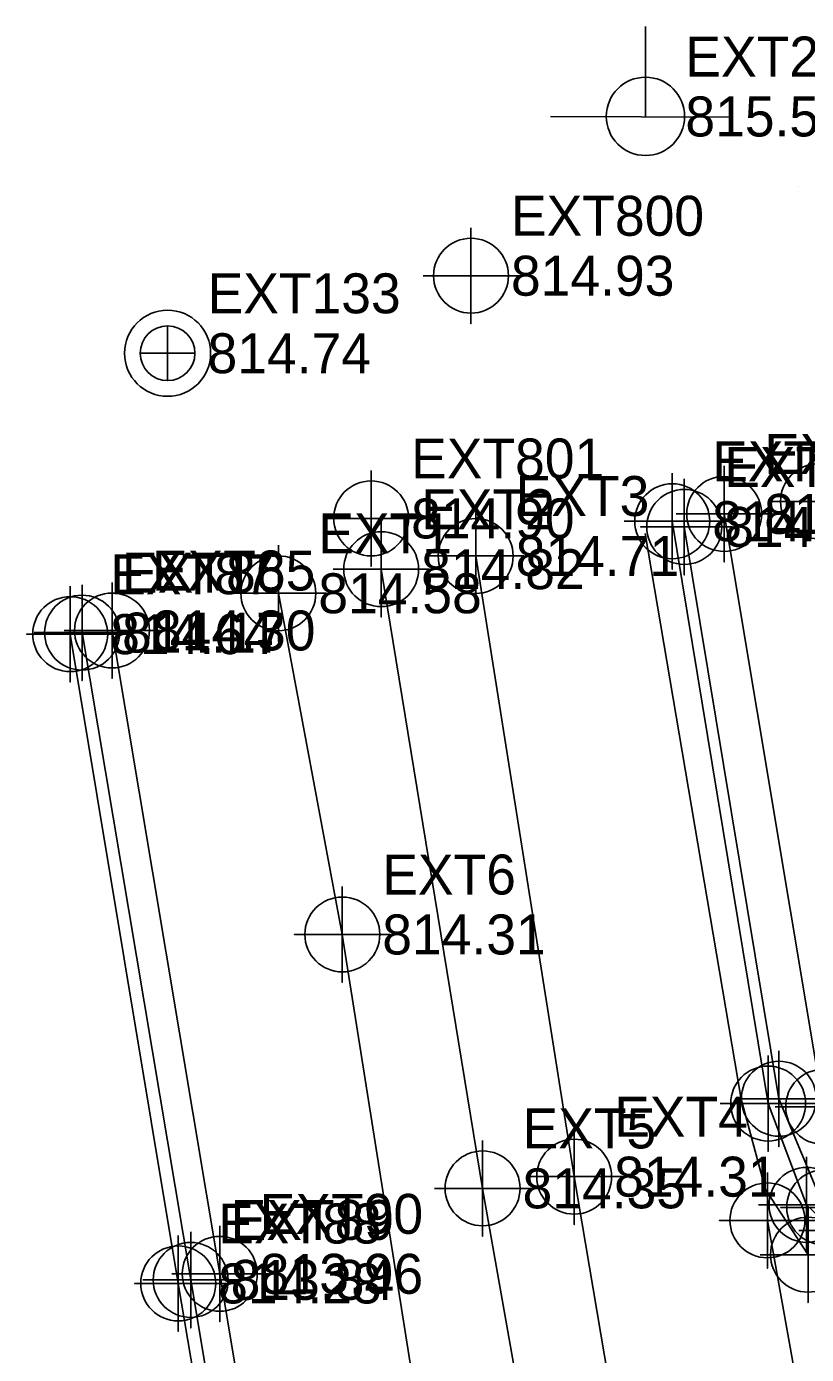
# Model space of a CAD drawing. Extents: x 1762120 to 1766775, y 709485 to 712965.
# Drawn here: x 1763761.7 to 1763810.5, y 712876.9 to 712960 of the extents above; entities that cross this region are included whole.
import ezdxf

# ---------------------------------------------------------------- set-up
doc = ezdxf.new("R2010")
doc.units = 0
for name, color, linetype in [('Exist DTM Crownline', 7, 'Continuous'), ('Exist DTM Crownline Cogo Elevation', 7, 'Continuous'), ('Exist DTM Crownline Cogo Number', 7, 'Continuous'), ('Exist DTM Crownline Cogo Point CELL', 7, 'Continuous'), ('Exist DTM Drainline', 7, 'Continuous'), ('Exist DTM Drainline Cogo Elevation', 7, 'Continuous'), ('Exist DTM Drainline Cogo Number', 7, 'Continuous'), ('Exist DTM Drainline Cogo Point CELL', 7, 'Continuous'), ('Exist DTM QL2 LIDAR Elevation Point', 7, 'Continuous'), ('Exist Roads Curbs', 7, 'Continuous'), ('Exist Roads Curbs Cogo Elevation', 7, 'Continuous'), ('Exist Roads Curbs Cogo Number', 7, 'Continuous'), ('Exist Roads Curbs Cogo Point CELL', 7, 'Continuous'), ('Exist Roads EOP', 7, 'Continuous'), ('Exist Roads EOP Cogo Elevation', 7, 'Continuous'), ('Exist Roads EOP Cogo Number', 7, 'Continuous'), ('Exist Roads EOP Cogo Point CELL', 7, 'Continuous'), ('Exist Roads EOP Other', 7, 'Continuous'), ('Exist Roads EOP Other Cogo Elevation', 7, 'Continuous'), ('Exist Roads EOP Other Cogo Number', 7, 'Continuous'), ('Exist Roads EOP Other Cogo Point CELL', 7, 'Continuous'), ('Exist Roads EOT', 7, 'Continuous'), ('Exist Roads EOT Cogo Elevation', 7, 'Continuous'), ('Exist Roads EOT Cogo Number', 7, 'Continuous'), ('Exist Roads EOT Cogo Point CELL', 7, 'Continuous'), ('Exist Utilities Power Joint Use Telephone CELL', 7, 'Continuous'), ('Exist Utilities Power Joint Use Telephone Cogo Elevation', 7, 'Continuous'), ('Exist Utilities Power Joint Use Telephone Cogo Number', 7, 'Continuous'), ('Exist Utilities Sanitary Sewer Manhole CELL', 7, 'Continuous'), ('Exist Utilities Sanitary Sewer Manhole Cogo Elevation', 7, 'Continuous'), ('Exist Utilities Sanitary Sewer Manhole Cogo Number', 7, 'Continuous'), ('Exist Utilities Sanitary Sewer UG Line Cogo Elevation', 7, 'Continuous'), ('Exist Utilities Sanitary Sewer UG Line Cogo Number', 7, 'Continuous'), ('Exist Utilities Sanitary Sewer UG Line Cogo Point CELL', 7, 'Continuous'), ('Exist Utilities Water UG Line SUE LOS C Cogo Elevation', 7, 'Continuous'), ('Exist Utilities Water UG Line SUE LOS C Cogo Number', 7, 'Continuous'), ('Exist Utilities Water UG Line SUE LOS C Cogo Point CELL', 7, 'Continuous')]:
    doc.layers.add(name, color=color, linetype=linetype)

msp = doc.modelspace()

# ---------------------------------------------------------------- linework, layer by layer
at = {"layer": 'Exist DTM Crownline'}
msp.add_lwpolyline([(1763783.92, 712926.058), (1763790.262, 712887.319), (1763795.183, 712859.532), (1763803.032, 712808.629), (1763808.926, 712776.275), (1763814.523, 712743.371), (1763820.27, 712708.85), (1763825.749, 712675.916), (1763832.222, 712637.522), (1763836.733, 712610.54), (1763843.626, 712568.925)], dxfattribs=at)
at = {"layer": 'Exist DTM Crownline Cogo Point CELL'}
for points in [[(1763783.92, 712929.058), (1763783.92, 712923.058), (1763783.92, 712926.058), (1763786.92, 712926.058), (1763780.92, 712926.058)], [(1763790.262, 712890.319), (1763790.262, 712884.319), (1763790.262, 712887.319), (1763793.262, 712887.319), (1763787.262, 712887.319)]]:
    msp.add_lwpolyline(points, dxfattribs=at)
for centre in [(1763783.92, 712926.058), (1763790.262, 712887.319)]:
    msp.add_circle(centre, 2.344, dxfattribs=at)
at = {"layer": 'Exist DTM Drainline'}
for points in [[(1763825.876, 712879.289), (1763821.264, 712879.254), (1763815.856, 712881.247), (1763810.53, 712886.287), (1763808.124, 712892.627), (1763802.125, 712929.057)], [(1763765.212, 712922.089), (1763772.003, 712881.594), (1763778.522, 712842.61), (1763780.745, 712828.822)]]:
    msp.add_lwpolyline(points, dxfattribs=at)
at = {"layer": 'Exist DTM Drainline Cogo Point CELL'}
for points in [[(1763802.125, 712932.057), (1763802.125, 712926.057), (1763802.125, 712929.057), (1763805.125, 712929.057), (1763799.125, 712929.057)], [(1763765.212, 712925.089), (1763765.212, 712919.089), (1763765.212, 712922.089), (1763768.212, 712922.089), (1763762.212, 712922.089)], [(1763808.124, 712895.627), (1763808.124, 712889.627), (1763808.124, 712892.627), (1763811.124, 712892.627), (1763805.124, 712892.627)], [(1763810.53, 712889.287), (1763810.53, 712883.287), (1763810.53, 712886.287), (1763813.53, 712886.287), (1763807.53, 712886.287)], [(1763772.003, 712884.594), (1763772.003, 712878.594), (1763772.003, 712881.594), (1763775.003, 712881.594), (1763769.003, 712881.594)]]:
    msp.add_lwpolyline(points, dxfattribs=at)
for centre in [(1763802.125, 712929.057), (1763765.212, 712922.089), (1763808.124, 712892.627), (1763810.53, 712886.287), (1763772.003, 712881.594)]:
    msp.add_circle(centre, 2.344, dxfattribs=at)
at = {"layer": 'Exist DTM QL2 LIDAR Elevation Point'}
msp.add_line((1763810, 712950), (1763810, 712950), dxfattribs=at)
at = {"layer": 'Exist Roads Curbs'}
for points in [[(1763844.782, 712885.226), (1763839.757, 712882.468), (1763825.898, 712880.05), (1763820.844, 712880.062), (1763816.547, 712881.733), (1763811.628, 712886.133), (1763808.794, 712892.927), (1763802.875, 712928.703)], [(1763764.468, 712921.993), (1763771.224, 712881.371), (1763777.799, 712842.52), (1763785.017, 712799.156), (1763793.002, 712751.297), (1763798.517, 712717.85), (1763798.751, 712716.41), (1763801.856, 712697.916), (1763802.154, 712696.936), (1763804.688, 712681.498), (1763811.149, 712642.967), (1763816.501, 712611.824), (1763823.372, 712570.121)]]:
    msp.add_lwpolyline(points, dxfattribs=at)
at = {"layer": 'Exist Roads Curbs Cogo Point CELL'}
for points in [[(1763802.875, 712931.703), (1763802.875, 712925.703), (1763802.875, 712928.703), (1763800.145, 712928.703), (1763805.875, 712928.703)], [(1763764.468, 712924.993), (1763764.468, 712918.993), (1763764.468, 712921.993), (1763761.738, 712921.993), (1763767.468, 712921.993)], [(1763808.794, 712895.927), (1763808.794, 712889.927), (1763808.794, 712892.927), (1763806.064, 712892.927), (1763811.794, 712892.927)], [(1763811.628, 712889.133), (1763811.628, 712883.133), (1763811.628, 712886.133), (1763808.898, 712886.133), (1763814.628, 712886.133)], [(1763771.224, 712884.371), (1763771.224, 712878.371), (1763771.224, 712881.371), (1763768.494, 712881.371), (1763774.224, 712881.371)]]:
    msp.add_lwpolyline(points, dxfattribs=at)
for centre in [(1763802.875, 712928.703), (1763764.468, 712921.993), (1763808.794, 712892.927), (1763811.628, 712886.133), (1763771.224, 712881.371)]:
    msp.add_circle(centre, 2.344, dxfattribs=at)
at = {"layer": 'Exist Roads EOP'}
for points in [[(1763810.619, 712883.17), (1763807.953, 712887.241), (1763806.443, 712892.894), (1763800.436, 712928.3)], [(1763767.083, 712922.223), (1763773.823, 712881.974), (1763780.335, 712842.895), (1763788.848, 712791.154), (1763795.539, 712751.806), (1763801.2, 712718.139), (1763807.385, 712682.013), (1763813.812, 712643.387), (1763818.936, 712612.35), (1763825.965, 712570.729)]]:
    msp.add_lwpolyline(points, dxfattribs=at)
at = {"layer": 'Exist Roads EOP Cogo Point CELL'}
for points in [[(1763767.083, 712925.223), (1763767.083, 712919.223), (1763767.083, 712922.223), (1763770.083, 712922.223), (1763764.083, 712922.223)], [(1763810.619, 712886.17), (1763810.619, 712880.17), (1763810.619, 712883.17), (1763813.619, 712883.17), (1763807.619, 712883.17)], [(1763773.823, 712884.974), (1763773.823, 712878.974), (1763773.823, 712881.974), (1763776.823, 712881.974), (1763770.823, 712881.974)]]:
    msp.add_lwpolyline(points, dxfattribs=at)
for centre in [(1763767.083, 712922.223), (1763810.619, 712883.17), (1763773.823, 712881.974)]:
    msp.add_circle(centre, 2.344, dxfattribs=at)
at = {"layer": 'Exist Roads EOP Other'}
msp.add_lwpolyline([(1763805.374, 712929.514), (1763811.566, 712892.422), (1763812.986, 712885.03)], dxfattribs=at)
at = {"layer": 'Exist Roads EOP Other Cogo Point CELL'}
for points in [[(1763811.242, 712933.302), (1763811.242, 712927.302), (1763811.242, 712930.302), (1763814.242, 712930.302), (1763808.242, 712930.302)], [(1763805.374, 712932.514), (1763805.374, 712926.514), (1763805.374, 712929.514), (1763808.374, 712929.514), (1763802.374, 712929.514)], [(1763811.566, 712895.422), (1763811.566, 712889.422), (1763811.566, 712892.422), (1763814.566, 712892.422), (1763808.566, 712892.422)], [(1763813.053, 712887.681), (1763813.053, 712881.681), (1763813.053, 712884.681), (1763816.053, 712884.681), (1763810.053, 712884.681)]]:
    msp.add_lwpolyline(points, dxfattribs=at)
for centre in [(1763811.242, 712930.302), (1763805.374, 712929.514), (1763811.566, 712892.422)]:
    msp.add_circle(centre, 2.344, dxfattribs=at)
at = {"layer": 'Exist Roads EOT'}
msp.add_line((1763815.792, 712842.322), (1763808.078, 712885.317), dxfattribs=at)
for points in [[(1763789.832, 712926.884), (1763795.992, 712888.052), (1763800.75, 712859.942), (1763807.254, 712820.955), (1763816.86, 712762.721), (1763822.148, 712731.849), (1763825.695, 712709.767), (1763831.213, 712676.817), (1763837.744, 712638.56), (1763842.2, 712611.183), (1763849.139, 712569.759)], [(1763777.488, 712924.55), (1763781.487, 712903.204), (1763789.164, 712854.697), (1763797.205, 712808.308), (1763802.541, 712775.258), (1763808.303, 712742.168), (1763814.095, 712707.894), (1763819.559, 712674.99), (1763826.1, 712636.377), (1763830.485, 712609.669), (1763837.441, 712567.81)]]:
    msp.add_lwpolyline(points, dxfattribs=at)
at = {"layer": 'Exist Roads EOT Cogo Point CELL'}
for points in [[(1763789.832, 712929.884), (1763789.832, 712923.884), (1763789.832, 712926.884), (1763786.832, 712926.884), (1763792.832, 712926.884)], [(1763777.488, 712927.55), (1763777.488, 712921.55), (1763777.488, 712924.55), (1763774.488, 712924.55), (1763780.488, 712924.55)], [(1763781.487, 712906.204), (1763781.487, 712900.204), (1763781.487, 712903.204), (1763778.487, 712903.204), (1763784.487, 712903.204)], [(1763795.992, 712891.052), (1763795.992, 712885.052), (1763795.992, 712888.052), (1763792.992, 712888.052), (1763798.992, 712888.052)], [(1763808.078, 712888.317), (1763808.078, 712882.317), (1763808.078, 712885.317), (1763805.078, 712885.317), (1763811.078, 712885.317)]]:
    msp.add_lwpolyline(points, dxfattribs=at)
for centre in [(1763789.832, 712926.884), (1763777.488, 712924.55), (1763781.487, 712903.204), (1763795.992, 712888.052), (1763808.078, 712885.317)]:
    msp.add_circle(centre, 2.344, dxfattribs=at)
at = {"layer": 'Exist Utilities Power Joint Use Telephone CELL'}
msp.add_line((1763800.447, 712954.381), (1763800.447, 712954.381), dxfattribs=at)
msp.add_lwpolyline([(1763794.509, 712954.381), (1763805.847, 712954.343), (1763800.447, 712954.361), (1763800.447, 712960.006)], dxfattribs=at)
msp.add_circle((1763800.448, 712954.387), 2.45, dxfattribs=at)
at = {"layer": 'Exist Utilities Sanitary Sewer Manhole CELL'}
msp.add_lwpolyline([(1763770.559, 712941.278), (1763770.559, 712937.853), (1763770.559, 712939.566), (1763772.272, 712939.566), (1763768.846, 712939.566)], dxfattribs=at)
for radius in [2.694, 1.712]:
    msp.add_circle((1763770.559, 712939.566), radius, dxfattribs=at)
at = {"layer": 'Exist Utilities Sanitary Sewer UG Line Cogo Point CELL'}
msp.add_lwpolyline([(1763789.537, 712947.418), (1763789.537, 712941.418), (1763789.537, 712944.418), (1763792.537, 712944.418), (1763786.537, 712944.418)], dxfattribs=at)
msp.add_circle((1763789.537, 712944.418), 2.344, dxfattribs=at)
at = {"layer": 'Exist Utilities Water UG Line SUE LOS C Cogo Point CELL'}
msp.add_lwpolyline([(1763783.292, 712932.232), (1763783.292, 712926.232), (1763783.292, 712929.232), (1763786.292, 712929.232), (1763780.292, 712929.232)], dxfattribs=at)
msp.add_circle((1763783.292, 712929.232), 2.344, dxfattribs=at)

# ---------------------------------------------------------------- texts
at = {"layer": 'Exist DTM Crownline Cogo Elevation'}
for s, p in [('814.82', (1763786.42, 712924.808)), ('814.35', (1763792.762, 712886.069))]:
    msp.add_text(s, height=2.5, dxfattribs=at).set_placement(p)
at = {"layer": 'Exist DTM Crownline Cogo Number'}
for s, p in [('EXT2', (1763786.42, 712928.558)), ('EXT5', (1763792.762, 712889.819))]:
    msp.add_text(s, height=2.5, dxfattribs=at).set_placement(p)
at = {"layer": 'Exist DTM Drainline Cogo Elevation'}
for s, p in [('814.36', (1763804.625, 712927.807)), ('814.17', (1763767.712, 712920.839)), ('813.84', (1763774.503, 712880.344))]:
    msp.add_text(s, height=2.5, dxfattribs=at).set_placement(p)
at = {"layer": 'Exist DTM Drainline Cogo Number'}
for s, p in [('EXT207', (1763804.625, 712931.557)), ('EXT86', (1763767.712, 712924.589)), ('EXT89', (1763774.503, 712884.094))]:
    msp.add_text(s, height=2.5, dxfattribs=at).set_placement(p)
at = {"layer": 'Exist Roads Curbs Cogo Elevation'}
for s, p in [('814.82', (1763805.375, 712927.453)), ('814.64', (1763766.968, 712920.743)), ('814.28', (1763773.724, 712880.121))]:
    msp.add_text(s, height=2.5, dxfattribs=at).set_placement(p)
at = {"layer": 'Exist Roads Curbs Cogo Number'}
for s, p in [('EXT201', (1763805.375, 712931.203)), ('EXT87', (1763766.968, 712924.493)), ('EXT88', (1763773.724, 712883.871))]:
    msp.add_text(s, height=2.5, dxfattribs=at).set_placement(p)
at = {"layer": 'Exist Roads EOP Cogo Elevation'}
for s, p in [('814.30', (1763769.583, 712920.973)), ('813.96', (1763776.323, 712880.724))]:
    msp.add_text(s, height=2.5, dxfattribs=at).set_placement(p)
at = {"layer": 'Exist Roads EOP Cogo Number'}
for s, p in [('EXT85', (1763769.583, 712924.723)), ('EXT90', (1763776.323, 712884.474))]:
    msp.add_text(s, height=2.5, dxfattribs=at).set_placement(p)
at = {"layer": 'Exist Roads EOP Other Cogo Elevation'}
msp.add_text('815.29', height=2.5, dxfattribs=at).set_placement((1763807.874, 712928.264))
at = {"layer": 'Exist Roads EOP Other Cogo Number'}
msp.add_text('EXT208', height=2.5, dxfattribs=at).set_placement((1763807.874, 712932.014))
at = {"layer": 'Exist Roads EOT Cogo Elevation'}
for s, p in [('814.71', (1763792.332, 712925.634)), ('814.58', (1763779.988, 712923.3)), ('814.31', (1763783.987, 712901.954)), ('814.31', (1763798.492, 712886.802))]:
    msp.add_text(s, height=2.5, dxfattribs=at).set_placement(p)
at = {"layer": 'Exist Roads EOT Cogo Number'}
for s, p in [('EXT3', (1763792.332, 712929.384)), ('EXT1', (1763779.988, 712927.05)), ('EXT6', (1763783.987, 712905.704)), ('EXT4', (1763798.492, 712890.552))]:
    msp.add_text(s, height=2.5, dxfattribs=at).set_placement(p)
at = {"layer": 'Exist Utilities Power Joint Use Telephone Cogo Elevation'}
msp.add_text('815.58', height=2.5, dxfattribs=at).set_placement((1763802.947, 712953.131))
at = {"layer": 'Exist Utilities Power Joint Use Telephone Cogo Number'}
msp.add_text('EXT277', height=2.5, dxfattribs=at).set_placement((1763802.947, 712956.881))
at = {"layer": 'Exist Utilities Sanitary Sewer Manhole Cogo Elevation'}
msp.add_text('814.74', height=2.5, dxfattribs=at).set_placement((1763773.059, 712938.316))
at = {"layer": 'Exist Utilities Sanitary Sewer Manhole Cogo Number'}
msp.add_text('EXT133', height=2.5, dxfattribs=at).set_placement((1763773.059, 712942.066))
at = {"layer": 'Exist Utilities Sanitary Sewer UG Line Cogo Elevation'}
msp.add_text('814.93', height=2.5, dxfattribs=at).set_placement((1763792.037, 712943.168))
at = {"layer": 'Exist Utilities Sanitary Sewer UG Line Cogo Number'}
msp.add_text('EXT800', height=2.5, dxfattribs=at).set_placement((1763792.037, 712946.918))
at = {"layer": 'Exist Utilities Water UG Line SUE LOS C Cogo Elevation'}
msp.add_text('814.90', height=2.5, dxfattribs=at).set_placement((1763785.792, 712927.982))
at = {"layer": 'Exist Utilities Water UG Line SUE LOS C Cogo Number'}
msp.add_text('EXT801', height=2.5, dxfattribs=at).set_placement((1763785.792, 712931.732))

doc.saveas('drawing.dxf')
